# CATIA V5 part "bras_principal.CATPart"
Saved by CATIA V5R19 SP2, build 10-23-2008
Part number: bras_principal
Bounding box of the stored display mesh (mm): x -50 to 50, y -45.301 to 45.301, z -1345.234 to 45.234
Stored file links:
  C:\Users\matthieu\Desktop\IAO\modele_CAO\bras_principal.CATPart
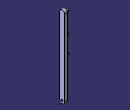
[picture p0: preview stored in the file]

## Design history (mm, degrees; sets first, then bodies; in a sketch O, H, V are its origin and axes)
Body1 (main body)
  Sketch1 on yz-plane, origin (0, 0, 0), H (0, 1, 0), V (0, 0, 1)
    circle A1 centre (0, 0) radius 15
    construction line L1 (0, 0) -> (0, -1300)
    point P1 (0, -1300)
    line L2 (45.3008, 0) -> (45.3008, -1300)
    line L3 (-45.3008, -1300) -> (-45.3008, 0)
    arc A2 centre (0, -1300) radius 45.3008 from (45.3008, -1300) to (-45.3008, -1300) cw
    arc A3 centre (0, 0) radius 45.3008 from (-45.3008, 0) to (45.3008, 0) cw
    circle A4 centre (0, -350) radius 15
    point P6 (0, -350)
    circle A5 centre (0, -650) radius 15
    point P7 (0, -650)
    circle A6 centre (0, -1300) radius 15
    radius A1 = 15
    distance L1 L2 = 45.3008
    radius A6 = 15
    radius A5 = 15
    radius A4 = 15
    distance H P6 = 350
    distance P6 P7 = 300
    distance P7 P1 = 650
    vertical: L1 V
    tangency: A2 L2, A3 L2, A2 L3, A3 L3
    coincidence: P6 L1, P7 L1
  MultiPad1: profile Sketch1, domains (length 50; length 0; length 50 / length 50; length 50 / length 50; length 50 / length 50)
